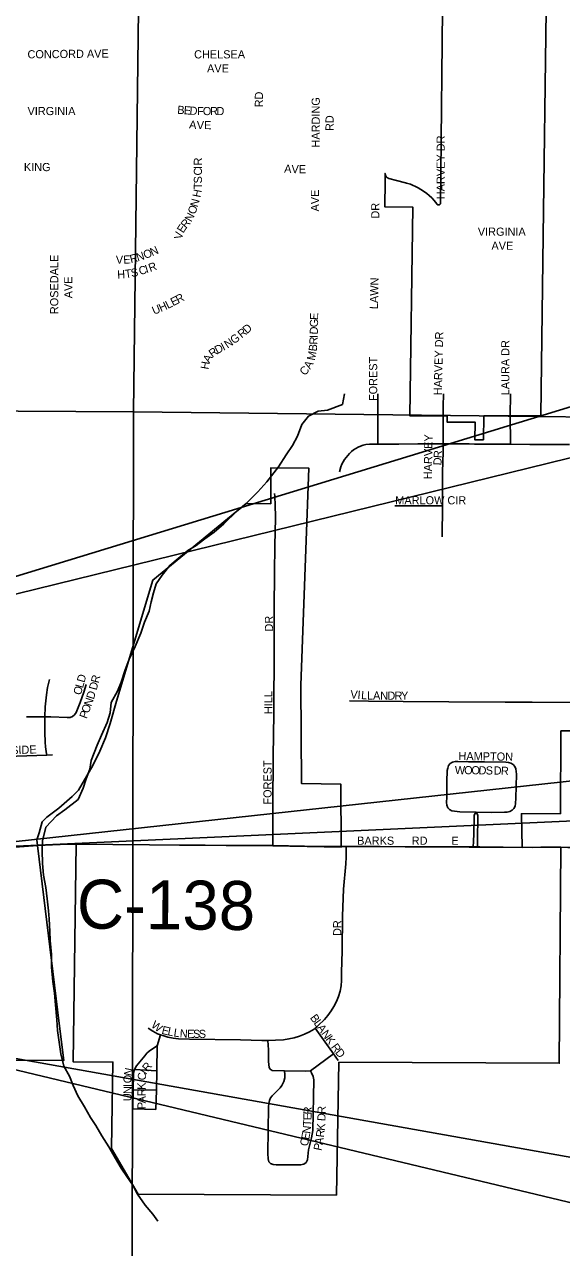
# Model space of a CAD drawing. Extents: x -9.1 to 34, y -3.1 to 22.
# Drawn here: x 6.099 to 6.722, y 17.795 to 19.215 of the extents above; entities that cross this region are included whole.
import ezdxf

# ---------------------------------------------------------------- set-up
doc = ezdxf.new("R2010")
doc.units = 0
for name, color, linetype in [('GM_X_City_Street', 7, 'Continuous'), ('GM_X_City_Street_Text', 7, 'Continuous'), ('GM_X_Corporation', 7, 'Continuous'), ('GM_X_County_Road', 7, 'Continuous'), ('GM_X_County_Road_Text', 7, 'Continuous'), ('GM_X_Minor_River', 7, 'Continuous'), ('GM_X_Section', 7, 'Continuous'), ('GM_X_Township_Subdivision', 7, 'Continuous'), ('GM_X_Township_Subdivision_Text', 7, 'Continuous'), ('SH_Text', 7, 'Continuous')]:
    doc.layers.add(name, color=color, linetype=linetype)

msp = doc.modelspace()

# ---------------------------------------------------------------- linework, layer by layer
at = {"layer": 'GM_X_City_Street'}
for points in [[(6.5088, 18.7274), (6.5091, 18.752), (6.5091, 18.7861)], [(6.5847, 18.7278), (6.5847, 18.7407), (6.5847, 18.753), (6.5847, 18.7606)], [(6.6629, 18.7274), (6.663, 18.7325), (6.6631, 18.7356), (6.6625, 18.754), (6.6625, 18.7606)], [(6.4644, 18.6954), (6.4662, 18.7013), (6.4673, 18.7042), (6.4687, 18.707), (6.4703, 18.7097), (6.4721, 18.7122), (6.4741, 18.7146), (6.4762, 18.7168), (6.4785, 18.719), (6.4809, 18.7209), (6.4835, 18.7227), (6.4862, 18.7242), (6.489, 18.7254), (6.492, 18.7264), (6.495, 18.7271), (6.4994, 18.7274), (6.5088, 18.7274)], [(6.5088, 18.7274), (6.5335, 18.7276), (6.5554, 18.7278), (6.5847, 18.7278)], [(6.5839, 18.656), (6.5841, 18.6956), (6.5843, 18.7065), (6.5847, 18.7188), (6.5847, 18.7278)], [(6.5847, 18.7278), (6.5993, 18.7278), (6.615, 18.7278), (6.6212, 18.7277), (6.6332, 18.7277), (6.6571, 18.7275), (6.6629, 18.7274)], [(6.6629, 18.7274), (6.6855, 18.7273), (6.6947, 18.7272), (6.7165, 18.7271), (6.7313, 18.7273)], [(6.5287, 18.6561), (6.5839, 18.656)], [(6.5837, 18.6202), (6.5839, 18.656)], [(6.1226, 18.4111), (6.1231, 18.4226), (6.1246, 18.4368), (6.1258, 18.4451), (6.1271, 18.4512), (6.1279, 18.4543)], [(6.1226, 18.4111), (6.1297, 18.4111), (6.1486, 18.4103), (6.1518, 18.4105), (6.1547, 18.4115), (6.1571, 18.4135), (6.1588, 18.4162), (6.1635, 18.4279), (6.1677, 18.4398), (6.1704, 18.4488)], [(6.4762, 18.4298), (6.498, 18.4294), (6.5384, 18.429), (6.5913, 18.4287), (6.6567, 18.4283), (6.6879, 18.4282), (6.7345, 18.4278), (6.7566, 18.4279)], [(6.1013, 18.411), (6.1139, 18.4111), (6.1226, 18.4111)], [(6.1247, 18.3666), (6.1244, 18.3684), (6.1234, 18.3765), (6.1231, 18.3819), (6.1226, 18.3931), (6.1225, 18.4074), (6.1226, 18.4111)], [(6.0264, 18.3631), (6.0314, 18.3633), (6.0783, 18.365), (6.1247, 18.3666)], [(6.1247, 18.3666), (6.1316, 18.3669)], [(6.623, 18.3004), (6.6406, 18.3003), (6.656, 18.3004), (6.6591, 18.3006), (6.6622, 18.3012), (6.6648, 18.3027), (6.6668, 18.3049), (6.6682, 18.3076), (6.6688, 18.3106), (6.6692, 18.3168), (6.6697, 18.3446), (6.6696, 18.3477), (6.6691, 18.3508), (6.668, 18.3536), (6.666, 18.3559), (6.6633, 18.3574), (6.6604, 18.3583), (6.6573, 18.3586), (6.6326, 18.359), (6.614, 18.359), (6.6017, 18.3594), (6.5986, 18.3592), (6.5956, 18.3585), (6.593, 18.3569), (6.5911, 18.3546), (6.59, 18.3517), (6.5895, 18.3487), (6.589, 18.3363), (6.5889, 18.3178), (6.5888, 18.3116), (6.5891, 18.3085), (6.5902, 18.3057), (6.5922, 18.3035), (6.5949, 18.3021), (6.598, 18.3015), (6.6042, 18.3011), (6.623, 18.3004)], [(6.6197, 18.2602), (6.6199, 18.2663), (6.6202, 18.2755), (6.6207, 18.2966), (6.6211, 18.2977), (6.6219, 18.299), (6.623, 18.3004)], [(6.6248, 18.2602), (6.6248, 18.2674), (6.6249, 18.2967), (6.6246, 18.2977), (6.6238, 18.2991), (6.623, 18.3004)], [(6.0582, 18.258), (6.0725, 18.2588), (6.1141, 18.2617)], [(6.4361, 18.0498), (6.4375, 18.0508), (6.4398, 18.0529), (6.447, 18.0599), (6.4511, 18.0646), (6.4548, 18.0698), (6.458, 18.0752), (6.4609, 18.0808), (6.4633, 18.0866), (6.4652, 18.0927), (6.4663, 18.0989), (6.4667, 18.1052), (6.4669, 18.1146), (6.4675, 18.1395), (6.4681, 18.18), (6.4692, 18.2111), (6.4718, 18.2406), (6.4721, 18.2484), (6.4721, 18.2577), (6.4721, 18.2608)], [(6.4668, 18.2608), (6.4721, 18.2608)], [(6.4721, 18.2608), (6.5115, 18.2608), (6.5826, 18.2603), (6.6197, 18.2602)], [(6.6197, 18.2602), (6.6248, 18.2602)], [(6.6248, 18.2602), (6.6274, 18.2602), (6.6543, 18.2598), (6.6764, 18.2597)], [(6.2425, 18.0498), (6.2477, 18.0463), (6.2505, 18.0448), (6.2534, 18.0434), (6.2566, 18.0422)], [(6.2528, 18.0293), (6.2566, 18.0422)], [(6.2566, 18.0422), (6.2593, 18.0412), (6.2654, 18.0395), (6.2716, 18.0382), (6.2778, 18.0375), (6.2903, 18.0371), (6.3496, 18.0363), (6.3745, 18.0356), (6.3815, 18.0356)], [(6.3815, 18.0356), (6.3902, 18.0358), (6.3996, 18.0364), (6.4058, 18.0373), (6.412, 18.0386), (6.418, 18.0405), (6.4238, 18.0429), (6.4295, 18.0457), (6.4349, 18.0489), (6.4361, 18.0498)], [(6.4575, 18.0201), (6.4361, 18.0498)], [(6.2266, 18.0019), (6.229, 18.0063), (6.2385, 18.0178), (6.2411, 18.0207), (6.2438, 18.0231), (6.25, 18.0274), (6.2528, 18.0293)], [(6.2525, 18.0004), (6.2528, 18.0293)], [(6.3815, 18.0356), (6.3822, 18.0246), (6.3821, 18.011), (6.383, 18.0042), (6.384, 18.0023), (6.3864, 18.0007), (6.4007, 18.0002)], [(6.4308, 18.0004), (6.4575, 18.0201)], [(6.4628, 18.0124), (6.4575, 18.0201)], [(6.2249, 17.9782), (6.2253, 17.9964), (6.2258, 17.9996), (6.2266, 18.0019)], [(6.2266, 18.0019), (6.2525, 18.0004)], [(6.2523, 17.9778), (6.2525, 18.0004)], [(6.4007, 18.0002), (6.4009, 17.996), (6.401, 17.9923), (6.4, 17.9878), (6.3977, 17.9833), (6.3956, 17.9808), (6.3864, 17.9714), (6.3846, 17.9689), (6.3833, 17.9658), (6.3824, 17.9624), (6.3821, 17.9585), (6.3812, 17.9045), (6.3816, 17.8983), (6.3826, 17.8948), (6.3845, 17.8927), (6.3876, 17.8916), (6.3911, 17.8912), (6.4193, 17.8912), (6.423, 17.8921), (6.4257, 17.894), (6.4273, 17.8972), (6.4287, 17.9088), (6.4321, 17.9227), (6.4336, 17.9311), (6.4348, 17.9899), (6.4341, 17.9937), (6.4321, 17.9979), (6.4308, 18.0004)], [(6.4007, 18.0002), (6.4256, 17.9998), (6.4308, 18.0004)], [(6.2246, 17.9561), (6.2249, 17.9782)], [(6.2249, 17.9782), (6.2523, 17.9778)], [(6.2515, 17.9555), (6.2523, 17.9778)], [(6.2246, 17.9561), (6.2515, 17.9555)]]:
    msp.add_lwpolyline(points, dxfattribs=at)
at = {"layer": 'GM_X_Corporation'}
for points in [[(6.5174, 19.0369), (6.5174, 19.0369), (6.5174, 19.0417), (6.5175, 19.0415), (6.5175, 19.0414), (6.5175, 19.0413), (6.5175, 19.0413), (6.5175, 19.0412), (6.5175, 19.0411), (6.5176, 19.041), (6.5176, 19.0409), (6.5176, 19.0408), (6.5176, 19.0407), (6.5176, 19.0406), (6.5176, 19.0405), (6.5177, 19.0404), (6.5177, 19.0403), (6.5177, 19.0402), (6.5177, 19.0401), (6.5178, 19.04), (6.5178, 19.04), (6.5178, 19.0399), (6.5178, 19.0398), (6.5179, 19.0397), (6.5179, 19.0396), (6.5179, 19.0395), (6.518, 19.0394), (6.518, 19.0393), (6.5181, 19.0392), (6.5181, 19.0392), (6.5181, 19.0391), (6.5182, 19.039), (6.5182, 19.0389), (6.5183, 19.0388), (6.5183, 19.0387), (6.5184, 19.0387), (6.5184, 19.0386), (6.5185, 19.0385), (6.5185, 19.0384), (6.5186, 19.0383), (6.5186, 19.0383), (6.5187, 19.0382), (6.5187, 19.0381), (6.5188, 19.038), (6.5188, 19.038), (6.5189, 19.0379), (6.519, 19.0378), (6.519, 19.0377), (6.5191, 19.0377), (6.5191, 19.0376), (6.5192, 19.0375), (6.5193, 19.0375), (6.5193, 19.0374), (6.5194, 19.0373), (6.5195, 19.0373), (6.5195, 19.0372), (6.5196, 19.0371), (6.5197, 19.0371), (6.5198, 19.037), (6.5198, 19.0369), (6.5199, 19.0369), (6.52, 19.0368), (6.52, 19.0368), (6.5201, 19.0367), (6.5202, 19.0367), (6.5203, 19.0366), (6.5204, 19.0365), (6.5204, 19.0365), (6.5205, 19.0364), (6.5206, 19.0364), (6.5207, 19.0363), (6.5208, 19.0363), (6.5208, 19.0363), (6.5209, 19.0362), (6.521, 19.0362), (6.5211, 19.0361), (6.5212, 19.0361), (6.5213, 19.036), (6.5214, 19.036), (6.5214, 19.036), (6.5215, 19.0359), (6.5216, 19.0359), (6.5217, 19.0359), (6.5218, 19.0358), (6.5219, 19.0357), (6.5307, 19.0335), (6.541, 19.0309), (6.5423, 19.0306), (6.5469, 19.0291), (6.5498, 19.0279), (6.552, 19.0269), (6.5556, 19.0249), (6.5619, 19.0212), (6.5658, 19.0183), (6.5686, 19.0162), (6.5716, 19.0135), (6.5743, 19.0103), (6.5773, 19.0065), (6.578, 19.0055), (6.578, 19.0055), (6.5781, 19.0054), (6.5782, 19.0054), (6.5783, 19.0053), (6.5784, 19.0053), (6.5785, 19.0052), (6.5785, 19.0052), (6.5786, 19.0052), (6.5787, 19.0052), (6.5788, 19.0051), (6.5789, 19.0051), (6.579, 19.0051), (6.5791, 19.0051), (6.5792, 19.0051), (6.5793, 19.0051), (6.5794, 19.0051), (6.5795, 19.0051), (6.5796, 19.0051), (6.5797, 19.0051), (6.5798, 19.0051), (6.5798, 19.0051), (6.5799, 19.0051), (6.58, 19.0052), (6.5801, 19.0052), (6.5802, 19.0052), (6.5803, 19.0053), (6.5804, 19.0053), (6.5805, 19.0054), (6.5805, 19.0054), (6.5806, 19.0055), (6.5807, 19.0055), (6.5808, 19.0056), (6.5808, 19.0056), (6.5809, 19.0057), (6.581, 19.0058), (6.581, 19.0058), (6.5811, 19.0059), (6.5812, 19.006), (6.5812, 19.0061), (6.5813, 19.0061), (6.5813, 19.0062), (6.5814, 19.0063), (6.5814, 19.0064), (6.5814, 19.0065), (6.5815, 19.0066), (6.5815, 19.0067), (6.5815, 19.0068), (6.5816, 19.0068), (6.5816, 19.0069), (6.5816, 19.007), (6.5816, 19.0071), (6.5816, 19.0074), (6.582, 19.0427), (6.5841, 19.2317)], [(6.7043, 19.2309), (6.701, 18.9693), (6.6981, 18.7609), (6.6625, 18.7606), (6.6318, 18.7604), (6.6315, 18.7326), (6.6215, 18.7326), (6.6219, 18.7532), (6.5895, 18.753), (6.5896, 18.7605), (6.5847, 18.7606), (6.546, 18.7605), (6.5495, 19.0026), (6.517, 19.003), (6.5173, 19.0329), (6.5174, 19.0369)], [(5.9683, 18.0127), (6.1445, 18.0123), (6.1391, 18.0553), (6.1141, 18.2617), (6.1132, 18.2686), (6.1159, 18.2767), (6.1194, 18.2892), (6.125, 18.2949), (6.1389, 18.3053), (6.1542, 18.3186), (6.1616, 18.326), (6.1784, 18.3547), (6.1863, 18.3713), (6.1929, 18.3866), (6.1983, 18.4035), (6.2057, 18.4295), (6.2479, 18.5699), (6.3563, 18.6588), (6.3847, 18.6585), (6.385, 18.7002), (6.4288, 18.6998), (6.4196, 18.448), (6.4204, 18.3336), (6.4662, 18.3329), (6.4665, 18.26), (6.387, 18.2613), (6.2442, 18.2626), (6.1589, 18.2632), (6.1553, 18.0109), (6.2016, 18.0105), (6.1998, 17.9102), (6.231, 17.8574), (6.4609, 17.8562), (6.4639, 18.0103), (6.7195, 18.0091), (6.7215, 18.2599), (6.6763, 18.2597), (6.6756, 18.2987), (6.721, 18.2988), (6.7215, 18.3948), (6.8153, 18.395)]]:
    msp.add_lwpolyline(points, dxfattribs=at)
at = {"layer": 'GM_X_County_Road'}
for points in [[(6.1141, 18.2617), (6.1404, 18.2629), (6.1589, 18.2632)], [(6.1589, 18.2632), (6.2442, 18.2626), (6.2789, 18.2624), (6.3085, 18.2621), (6.3329, 18.262), (6.3575, 18.2618), (6.3814, 18.2618), (6.387, 18.2617)], [(6.387, 18.2617), (6.424, 18.2611), (6.4668, 18.2608)], [(6.4668, 18.2606), (6.689, 18.2596), (6.698, 18.2598), (6.7071, 18.2599), (6.712, 18.2599), (6.7215, 18.2599)], [(6.7215, 18.2599), (6.7295, 18.2596), (6.7478, 18.2597), (6.8149, 18.2595)]]:
    msp.add_lwpolyline(points, dxfattribs=at)
at = {"layer": 'GM_X_Minor_River'}
for points in [[(6.4702, 18.7861), (6.4678, 18.7736), (6.4507, 18.767), (6.4397, 18.7657), (6.4286, 18.7601), (6.4209, 18.7504), (6.4158, 18.7368), (6.4099, 18.7259), (6.4026, 18.715), (6.3937, 18.7011), (6.3802, 18.6838), (6.3698, 18.6722), (6.3548, 18.6573), (6.3453, 18.6498), (6.3303, 18.6352), (6.3192, 18.6255), (6.3084, 18.6177), (6.2981, 18.6099), (6.2886, 18.604), (6.2771, 18.595), (6.2675, 18.5868), (6.2586, 18.5756), (6.2517, 18.5654), (6.2485, 18.5552), (6.2461, 18.5447), (6.2436, 18.5337), (6.2382, 18.5209), (6.2338, 18.5084), (6.2272, 18.4926), (6.2205, 18.4779), (6.2158, 18.4655), (6.2111, 18.4515), (6.2068, 18.441), (6.1994, 18.4278), (6.1985, 18.4157), (6.1949, 18.4047), (6.1883, 18.39), (6.1832, 18.3784), (6.1765, 18.3603), (6.1748, 18.3504), (6.1705, 18.3391), (6.167, 18.3282), (6.1611, 18.3154), (6.1458, 18.3031), (6.1362, 18.2964), (6.1239, 18.2833), (6.1199, 18.2674), (6.1194, 18.256), (6.1199, 18.2409), (6.1209, 18.2276), (6.1237, 18.2131), (6.1254, 18.1998), (6.1267, 18.1862), (6.1274, 18.1767), (6.1283, 18.1619), (6.1289, 18.1517), (6.1302, 18.1353), (6.1304, 18.1206), (6.1317, 18.1039), (6.1338, 18.0906), (6.1351, 18.0769), (6.1364, 18.0594), (6.1373, 18.0473), (6.1394, 18.031)], [(6.1394, 18.031), (6.1411, 18.0199), (6.1447, 18.0059), (6.151, 17.994), (6.1554, 17.9834), (6.1609, 17.9712), (6.1687, 17.9585), (6.1757, 17.9463), (6.1817, 17.9368), (6.1887, 17.9249), (6.1968, 17.9123), (6.2046, 17.8985), (6.2113, 17.8874), (6.2176, 17.8779), (6.2246, 17.8676), (6.2302, 17.8572), (6.2391, 17.8446), (6.248, 17.8342), (6.2535, 17.8259)]]:
    msp.add_lwpolyline(points, dxfattribs=at)
at = {"layer": 'GM_X_Section'}
for points in [[(5.226, 19.7723), (6.2379, 19.7608), (6.2253, 18.7649), (5.2207, 18.771)], [(6.2379, 19.7608), (7.2408, 19.7107), (7.2285, 18.7534), (6.2253, 18.7649)], [(5.2207, 18.771), (6.2253, 18.7649), (6.224, 17.7617), (5.2149, 17.764)], [(6.2253, 18.7649), (7.2285, 18.7534), (7.2227, 17.7567), (6.224, 17.7617)]]:
    msp.add_lwpolyline(points, close=True, dxfattribs=at)
at = {"layer": 'GM_X_Township_Subdivision'}
for points in [[(6.5847, 18.7606), (6.5849, 18.7724), (6.585, 18.7847), (6.585, 18.7861)], [(6.6625, 18.7606), (6.663, 18.7861)], [(6.3898, 18.659), (6.3896, 18.6644), (6.3893, 18.6674), (6.3889, 18.6704)], [(6.387, 18.2617), (6.387, 18.269), (6.3871, 18.307), (6.3876, 18.3657), (6.3881, 18.4145), (6.3882, 18.4299), (6.3884, 18.4485), (6.3885, 18.4577), (6.3886, 18.4731), (6.3886, 18.4916), (6.3888, 18.5367), (6.389, 18.5782), (6.3895, 18.6101), (6.3901, 18.6418), (6.3898, 18.6584), (6.3898, 18.659)]]:
    msp.add_lwpolyline(points, dxfattribs=at)
at = {"layer": 'SH_Text'}
for points in [[(9.6799, 19.6726), (5.7467, 18.4697), (9.6799, 19.4366)], [(9.7171, 18.426), (6.0037, 18.2573), (9.7171, 18.662)], [(9.7227, 17.3677), (5.8733, 18.0531), (9.7227, 17.1316)]]:
    msp.add_lwpolyline(points, close=True, dxfattribs=at)

# ---------------------------------------------------------------- texts
at = {"layer": 'GM_X_City_Street_Text'}
for s, rotation, p in [('CONCORD AVE', 0.5781, (6.1025, 19.1752)), ('CHELSEA', 0, (6.2958, 19.1752)), ('AVE', 0, (6.3108, 19.1589)), ('RD', 90, (6.3757, 19.1184)), ('VIRGINIA', 0, (6.1025, 19.1094)), ('B', 355.6497, (6.276, 19.111)), ('E', 355.6463, (6.2835, 19.1105)), ('D', 356.6039, (6.2903, 19.11)), ('F', 359.4676, (6.2991, 19.1094)), ('O', 359.9703, (6.3059, 19.1094)), ('R', 359.9941, (6.3142, 19.1094)), ('D', 359.9929, (6.3217, 19.1094)), ('HARDING', 90, (6.4416, 19.0718)), ('RD', 90, (6.4577, 19.0909)), ('A', 354.7027, (6.2897, 19.094)), ('V', 359.0244, (6.2988, 19.0932)), ('E', 359.9457, (6.3073, 19.0931)), ('KING', 0, (6.0983, 19.0444)), ('C', 89.994, (6.3049, 19.0393)), ('R', 90, (6.3049, 19.051)), ('I', 90, (6.3049, 19.0468)), ('A', 356.7195, (6.4001, 19.0427)), ('V', 357.831, (6.4086, 19.0422)), ('E', 359.8075, (6.4173, 19.0419)), ('S', 89.9956, (6.3049, 19.0301)), ('H', 78.7483, (6.303, 19.0133)), ('T', 89.6942, (6.3049, 19.0234)), ('AVE', 90, (6.4407, 18.9976)), ('O', 71.1871, (6.297, 18.9936)), ('N', 74.124, (6.2999, 19.002)), ('DR', 90, (6.5107, 18.9893)), ('N', 62.5887, (6.2926, 18.9848)), ('E', 57.1055, (6.2831, 18.9718)), ('R', 50.0203, (6.2865, 18.9772)), ('V', 76.6581, (6.2815, 18.9645)), ('R', 13.9156, (6.2224, 18.9376)), ('N', 17.6652, (6.2304, 18.9395)), ('O', 21.7655, (6.239, 18.9423)), ('N', 24.5106, (6.2472, 18.9456)), ('ROSEDALE', 90, (6.1382, 18.8784)), ('V', 0.3279, (6.205, 18.9369)), ('E', 2.8916, (6.2138, 18.9369)), ('C', 17.5588, (6.2332, 18.9236)), ('I', 17.8916, (6.2405, 18.9259)), ('R', 19.9096, (6.2448, 18.9273)), ('AVE', 90, (6.1545, 18.8968)), ('H', 2.9301, (6.2068, 18.9197)), ('T', 8.0883, (6.2161, 18.9203)), ('S', 11.5204, (6.2233, 18.9213)), ('LAWN', 88.9012, (6.5091, 18.8842)), ('H', 23.7649, (6.2572, 18.8809)), ('L', 26.9175, (6.2654, 18.8844)), ('E', 27.4803, (6.2714, 18.8875)), ('R', 27.5154, (6.2773, 18.8906)), ('U', 22.4753, (6.2493, 18.8776)), ('E', 88.7901, (6.4396, 18.8715)), ('D', 41.5596, (6.3571, 18.8551)), ('D', 88.7767, (6.4393, 18.8548)), ('G', 88.7879, (6.4395, 18.8632)), ('N', 33.8769, (6.3346, 18.8383)), ('G', 37.2186, (6.3421, 18.8433)), ('R', 39.4143, (6.351, 18.8501)), ('R', 87.0697, (6.4388, 18.8429)), ('I', 88.2965, (6.4392, 18.8506)), ('R', 35.4615, (6.3169, 18.8277)), ('D', 28.4517, (6.3227, 18.8319)), ('I', 27.8746, (6.33, 18.8358)), ('M', 78.5247, (6.4358, 18.8241)), ('B', 84.1115, (6.438, 18.8349)), ('H', 80.3832, (6.3124, 18.8138)), ('A', 60.247, (6.3135, 18.8212)), ('A', 60.1923, (6.4305, 18.8138)), ('FOREST', 90, (6.5082, 18.7776)), ('C', 47.5254, (6.4241, 18.8064)), ('HARVEY', 89.0323, (6.5716, 18.6868)), ('D', 87.0044, (6.5827, 18.7028)), ('R', 87.2889, (6.5831, 18.7112)), ('MARLOW CIR', 0, (6.5292, 18.6577)), ('D', 74.3451, (6.1685, 18.4503)), ('D', 74.9239, (6.1826, 18.4415)), ('R', 75.8719, (6.1849, 18.4497)), ('O', 72.8298, (6.1642, 18.4357)), ('L', 74.1332, (6.1667, 18.4439)), ('D', 72.562, (6.1793, 18.4308)), ('V', 355.6683, (6.4768, 18.4327)), ('I', 355.6525, (6.4851, 18.4321)), ('L', 355.8871, (6.4893, 18.4318)), ('L', 358.323, (6.4964, 18.4313)), ('A', 359.9028, (6.5034, 18.4311)), ('N', 359.9929, (6.5117, 18.431)), ('D', 359.9929, (6.52, 18.431)), ('R', 359.9941, (6.5284, 18.431)), ('Y', 359.9929, (6.5359, 18.431)), ('O', 69.535, (6.1734, 18.4146)), ('N', 70.5531, (6.1764, 18.4226)), ('P', 69.4567, (6.1711, 18.4083)), ('BAYSIDE', 1.9081, (6.0583, 18.3669)), ('HAMPTON', 359.1689, (6.6025, 18.361)), ('W', 359.2435, (6.5983, 18.3447)), ('O', 359.2495, (6.6091, 18.3446)), ('O', 359.2495, (6.6175, 18.3445)), ('D', 359.2495, (6.6258, 18.3444)), ('S', 359.235, (6.6341, 18.3443)), ('D', 359.1912, (6.6433, 18.3442)), ('R', 357.425, (6.6516, 18.344)), ('BARKS', 0, (6.485, 18.2627)), ('RD', 0, (6.5483, 18.2627)), ('E', 0, (6.5942, 18.2627)), ('DR', 90, (6.4666, 18.1568)), ('W', 323.5437, (6.2451, 18.0517)), ('B', 305.5631, (6.4298, 18.0619)), ('L', 305.5694, (6.4341, 18.0558)), ('E', 345.6537, (6.2574, 18.0435)), ('L', 348.4328, (6.2644, 18.0418)), ('L', 351.9883, (6.2716, 18.0403)), ('N', 356.3898, (6.2789, 18.0393)), ('E', 358.4363, (6.2876, 18.0388)), ('S', 359.7191, (6.2945, 18.0386)), ('S', 359.9956, (6.3012, 18.0385)), ('A', 305.5678, (6.438, 18.0504)), ('N', 305.5835, (6.4429, 18.0436)), ('K', 305.5758, (6.4477, 18.0369)), ('R', 306.2224, (6.4541, 18.0279)), ('D', 310.1419, (6.4589, 18.0213)), ('N', 78.6901, (6.2233, 17.9938)), ('C', 84.4054, (6.2395, 17.989)), ('I', 57.4618, (6.2399, 17.9954)), ('R', 51.5564, (6.242, 17.9987)), ('O', 89.6939, (6.2233, 17.9859)), ('I', 89.7098, (6.2233, 17.9817)), ('K', 89.847, (6.2395, 17.9784)), ('N', 89.6887, (6.2233, 17.9734)), ('U', 89.6939, (6.2232, 17.9651)), ('R', 90, (6.2395, 17.9709)), ('A', 90, (6.2395, 17.9626)), ('P', 90, (6.2395, 17.9559)), ('R', 88.3163, (6.4321, 17.9496)), ('R', 88.3665, (6.4484, 17.9503)), ('T', 86.6353, (6.4315, 17.9359)), ('E', 88.3163, (6.4319, 17.9429)), ('D', 87.9886, (6.4481, 17.9419)), ('E', 79.9112, (6.4292, 17.9199)), ('N', 83.2733, (6.4305, 17.9271)), ('R', 82.7448, (6.4463, 17.9227)), ('K', 85.2182, (6.4473, 17.9306)), ('C', 78.2302, (6.4276, 17.9123)), ('P', 78.7543, (6.4434, 17.9072)), ('A', 79.8309, (6.4447, 17.914))]:
    msp.add_text(s, height=0.00947, rotation=rotation, dxfattribs=at).set_placement(p)
at = {"layer": 'GM_X_County_Road_Text'}
msp.add_text('C-138', height=0.05682, rotation=359.4489, dxfattribs=at).set_placement((6.1595, 18.1656))
at = {"layer": 'GM_X_Township_Subdivision_Text'}
for s, rotation, p in [('HARVEY DR', 90, (6.5866, 19.0118)), ('VIRGINIA', 0, (6.625, 18.9694)), ('AVE', 0, (6.6408, 18.9531)), ('HARVEY DR', 88.6031, (6.5832, 18.7842)), ('LAURA DR', 90, (6.6616, 18.7843)), ('DR', 90, (6.3874, 18.5101)), ('HILL', 90, (6.3866, 18.4143)), ('FOREST', 90, (6.3857, 18.3093))]:
    msp.add_text(s, height=0.00947, rotation=rotation, dxfattribs=at).set_placement(p)

doc.saveas('drawing.dxf')
